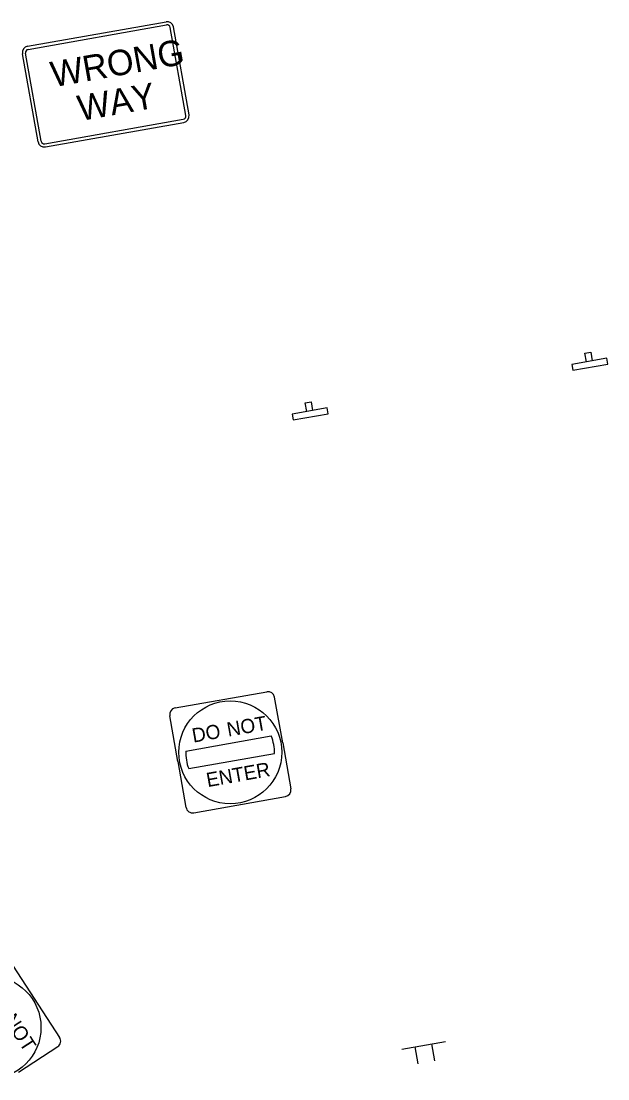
# Model space of a CAD drawing. Extents: x 1581789 to 1622364, y 1043167 to 1103486.
# Drawn here: x 1611935.6 to 1612073.3, y 1090792.9 to 1091041.3 of the extents above; entities that cross this region are included whole.
import ezdxf

# ---------------------------------------------------------------- set-up
doc = ezdxf.new("R2010")
doc.units = 0
doc.layers.add('RD_PD_ALT1_TX', color=7, linetype='Continuous')

msp = doc.modelspace()

# ---------------------------------------------------------------- linework, layer by layer
at = {"layer": 'RD_PD_ALT1_TX'}
for p, q in [((1611937.07, 1091035.36), (1611969.56, 1091041.13)), ((1611937.2, 1091034.62), (1611969.7, 1091040.39)), ((1611974.23, 1091019.1), (1611970.57, 1091039.78)), ((1611974.97, 1091019.23), (1611971.3, 1091039.91)), ((1611939.52, 1091012.95), (1611935.86, 1091033.62)), ((1611940.26, 1091013.08), (1611936.6, 1091033.75)), ((1611941.13, 1091012.47), (1611973.62, 1091018.23)), ((1611941.26, 1091011.73), (1611973.76, 1091017.49)), ((1611971.7, 1090879.96), (1611993.24, 1090883.78)), ((1611996.96, 1090871.74), (1611995.05, 1090882.51)), ((1611972.34, 1090867.37), (1611970.43, 1090878.14)), ((1611974.22, 1090869.82), (1611994.26, 1090873.38)), ((1611996.96, 1090871.74), (1611998.87, 1090860.97)), ((1611974.89, 1090865.71), (1611995.04, 1090869.29)), ((1611972.34, 1090867.37), (1611974.25, 1090856.6)), ((1611976.06, 1090855.34), (1611997.6, 1090859.16)), ((1611932.68, 1090820.92), (1611944.6, 1090802.58)), ((1612024.87, 1090799.79), (1612035.14, 1090801.62)), ((1611934.97, 1090794.45), (1611944.15, 1090800.42)), ((1612027.94, 1090800.34), (1612028.64, 1090796.41)), ((1612031.9, 1090801.04), (1612032.59, 1090797.11))]:
    msp.add_line(p, q, dxfattribs=at)
for points in [[(1612067.86, 1090963.29), (1612069.23, 1090963.53), (1612069.59, 1090961.48), (1612068.22, 1090961.24)], [(1612065.05, 1090959.26), (1612073.25, 1090960.72), (1612073.01, 1090962.09), (1612064.8, 1090960.63)], [(1612002.22, 1090951.65), (1612003.59, 1090951.89), (1612003.95, 1090949.84), (1612002.58, 1090949.59)], [(1611999.41, 1090947.62), (1612007.61, 1090949.08), (1612007.37, 1090950.44), (1611999.16, 1090948.99)]]:
    msp.add_lwpolyline(points, close=True, dxfattribs=at)
for centre in [(1611984.64, 1090869.54), (1611928.14, 1090804.94)]:
    msp.add_circle(centre, 12.08, dxfattribs=at)
for centre, radius, start, end in [((1611993.51, 1090882.24), 1.56, 10.0581, 100.0581), ((1611971.97, 1090878.42), 1.56, 100.0581, 190.0581), ((1611984.63, 1090869.4), 10.42, 359.383, 22.4595), ((1611984.63, 1090869.4), 10.42, 177.6566, 200.7332), ((1611997.33, 1090860.7), 1.56, 280.0581, 10.0581), ((1611975.79, 1090856.88), 1.56, 190.0581, 280.0581), ((1611943.29, 1090801.72), 1.56, 303.0275, 33.0275)]:
    msp.add_arc(centre, radius, start, end, dxfattribs=at)
for centre, major_axis, start_param, end_param in [((1611969.83, 1091039.65), (1.48, 0.26), 0, 1.570796), ((1611969.83, 1091039.65), (0.738, 0.131), 0, 1.570796), ((1611937.33, 1091033.88), (-1.48, -0.26), 4.712389, 6.283185), ((1611937.33, 1091033.88), (-0.738, -0.131), 4.712389, 6.283185), ((1611973.49, 1091018.97), (0.738, 0.131), 4.712389, 6.283185), ((1611973.49, 1091018.97), (1.48, 0.26), 4.712389, 6.283185), ((1611941, 1091013.21), (-1.48, -0.26), 0, 1.570796), ((1611941, 1091013.21), (-0.738, -0.131), 0, 1.570796)]:
    msp.add_ellipse(centre, major_axis=major_axis, ratio=0.999906, start_param=start_param, end_param=end_param, dxfattribs=at)

# ---------------------------------------------------------------- texts
for s, height, rotation, p in [('WRONG', 5.999, 10.058, (1611943.09, 1091025.73)), ('WAY', 5.999, 10.058, (1611949.4, 1091017.79)), ('DO', 3.332, 10.0581, (1611975.98, 1090871.8)), ('NOT', 3.332, 10.0581, (1611984.16, 1090873.22)), ('ENTER', 3.334, 10.0581, (1611979.34, 1090861.36)), ('NOT', 3.332, 303.0275, (1611931.34, 1090806.81))]:
    msp.add_text(s, height=height, rotation=rotation, dxfattribs=at).set_placement(p)

doc.saveas('drawing.dxf')
